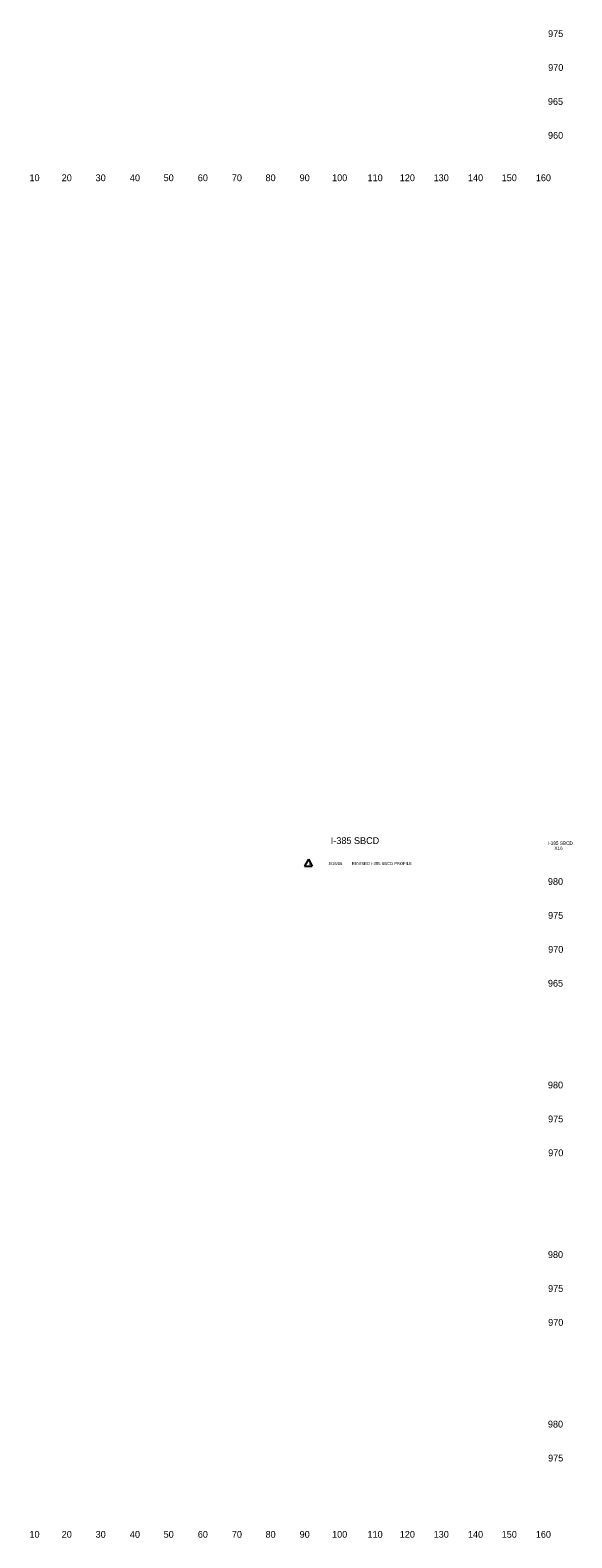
# Model space of a CAD drawing. Extents: x 4994 to 6876, y 4997 to 8804.
# Drawn here: x 5684.1 to 5843.7, y 6997.5 to 7442 of the extents above; entities that cross this region are included whole.
import ezdxf

# ---------------------------------------------------------------- set-up
doc = ezdxf.new("R2010")
doc.units = 0
for name, color, linetype in [('RD_SHT_ID', 7, 'Continuous'), ('RD_SHT_TX', 7, 'Continuous'), ('RD_XS_TX_Offset', 7, 'Continuous')]:
    doc.layers.add(name, color=color, linetype=linetype)

msp = doc.modelspace()

# ---------------------------------------------------------------- linework, layer by layer
at = {"layer": 'RD_SHT_TX'}
for p, q in [((5766.08, 7197.59), (5764.94, 7195.56)), ((5766.08, 7197.59), (5767.22, 7195.56)), ((5764.94, 7195.56), (5767.22, 7195.56))]:
    msp.add_line(p, q, dxfattribs=at)

# ---------------------------------------------------------------- texts
at = {"layer": 'RD_SHT_ID'}
for s, height, p in [('I-385 SBCD', 2, (5772.69, 7202.06)), ('I-385 SBCD', 1, (5836.63, 7201.8)), ('X16', 1, (5838.55, 7200.3))]:
    msp.add_text(s, height=height, dxfattribs=at).set_placement(p)
at = {"layer": 'RD_SHT_TX'}
for s, p in [('1', (5766.08, 7195.89)), ('5/16/16', (5772.04, 7195.85)), ('REVISED I-385 SBCD PROFILE', (5778.87, 7195.85))]:
    msp.add_text(s, height=0.88, dxfattribs=at).set_placement(p)
at = {"layer": 'RD_XS_TX_Offset'}
for s, p in [('975', (5836.71, 7440)), ('970', (5836.74, 7430)), ('965', (5836.66, 7420)), ('960', (5836.69, 7410)), ('10', (5683.91, 7397.5)), ('20', (5693.4, 7397.5)), ('30', (5703.39, 7397.5)), ('40', (5713.5, 7397.5)), ('50', (5723.43, 7397.5)), ('60', (5733.5, 7397.5)), ('70', (5743.54, 7397.5)), ('80', (5753.46, 7397.5)), ('90', (5763.5, 7397.5)), ('100', (5773.07, 7397.5)), ('110', (5783.51, 7397.5)), ('120', (5793.01, 7397.5)), ('130', (5802.99, 7397.5)), ('140', (5813.1, 7397.5)), ('150', (5823.04, 7397.5)), ('160', (5833.1, 7397.5)), ('980', (5836.66, 7190)), ('975', (5836.71, 7180)), ('970', (5836.74, 7170)), ('965', (5836.66, 7160)), ('980', (5836.66, 7130)), ('975', (5836.71, 7120)), ('970', (5836.74, 7110)), ('980', (5836.66, 7080)), ('975', (5836.71, 7070)), ('970', (5836.74, 7060)), ('980', (5836.66, 7030)), ('975', (5836.71, 7020)), ('10', (5683.91, 6997.5)), ('20', (5693.4, 6997.5)), ('30', (5703.39, 6997.5)), ('40', (5713.5, 6997.5)), ('50', (5723.43, 6997.5)), ('60', (5733.5, 6997.5)), ('70', (5743.54, 6997.5)), ('80', (5753.46, 6997.5)), ('90', (5763.5, 6997.5)), ('100', (5773.07, 6997.5)), ('110', (5783.51, 6997.5)), ('120', (5793.01, 6997.5)), ('130', (5802.99, 6997.5)), ('140', (5813.1, 6997.5)), ('150', (5823.04, 6997.5)), ('160', (5833.1, 6997.5))]:
    msp.add_text(s, height=2, dxfattribs=at).set_placement(p)

doc.saveas('drawing.dxf')
